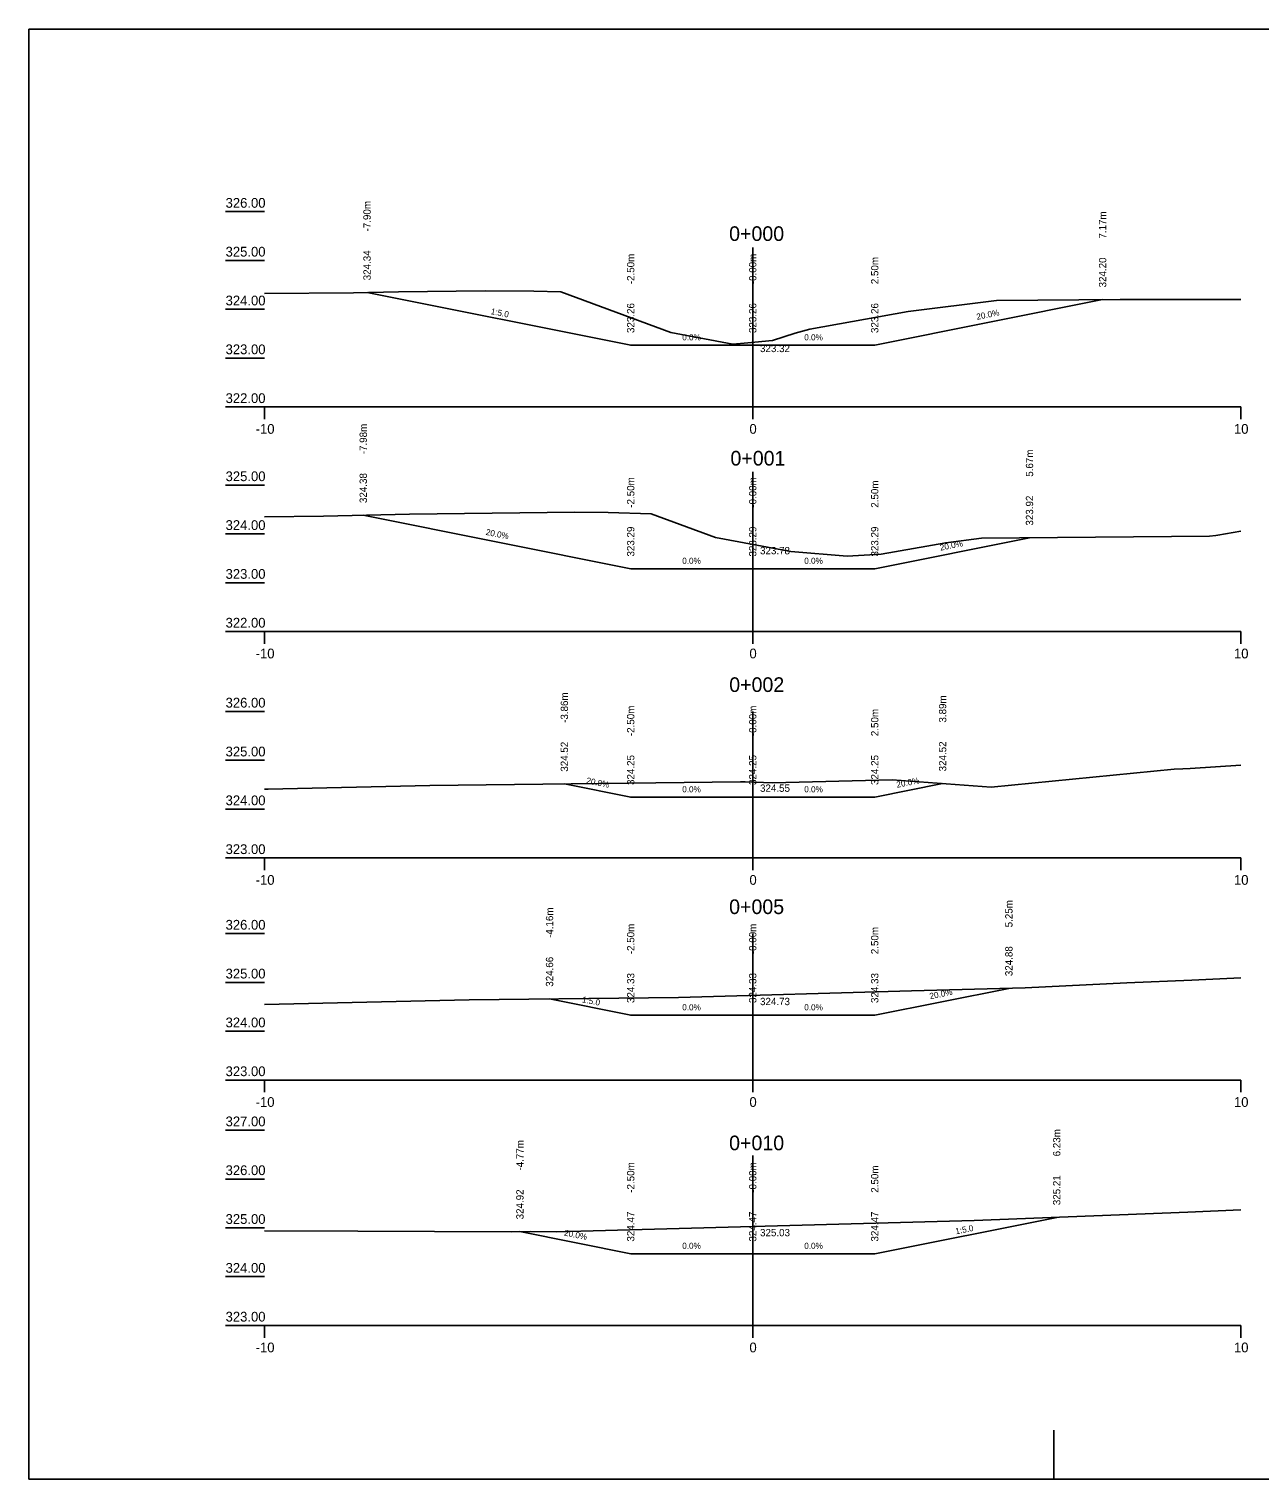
# Model space of a CAD drawing. Extents: x -559238.7 to -559196.7, y -1164066.1 to -1164036.4.
# Drawn here: x -559238.68 to -559213.47, y -1164066.1 to -1164036.4 of the extents above; entities that cross this region are included whole.
import ezdxf

# ---------------------------------------------------------------- set-up
doc = ezdxf.new("R2010")
doc.units = 0
for name, color, linetype in [('16', 7, 'Continuous'), ('21', 7, 'Continuous'), ('28', 7, 'Continuous'), ('59', 7, 'Continuous'), ('Body pricny rez', 7, 'Continuous'), ('Popis pricneho profilu', 7, 'Continuous')]:
    doc.layers.add(name, color=color, linetype=linetype)

msp = doc.modelspace()

# ---------------------------------------------------------------- linework, layer by layer
for p, q in [((-559196.676, -1164036.404), (-559238.676, -1164036.404)), ((-559238.676, -1164036.404), (-559238.676, -1164066.104)), ((-559217.676, -1164066.104), (-559217.676, -1164065.104)), ((-559238.676, -1164066.104), (-559196.676, -1164066.104))]:
    msp.add_line(p, q)
for points in [[(-559233.848, -1164041.823), (-559232.028, -1164041.807), (-559231.104, -1164041.786), (-559229.33, -1164041.765), (-559228.333, -1164041.773), (-559227.78, -1164041.79), (-559225.524, -1164042.623), (-559224.257, -1164042.858), (-559223.945, -1164042.831), (-559223.444, -1164042.783), (-559222.976, -1164042.631), (-559222.675, -1164042.551), (-559220.661, -1164042.192), (-559218.852, -1164041.967), (-559216.316, -1164041.944), (-559214.505, -1164041.941), (-559213.848, -1164041.943)], [(-559231.75, -1164041.801), (-559226.348, -1164042.881), (-559223.848, -1164042.881), (-559221.348, -1164042.881), (-559216.679, -1164041.947)], [(-559226.348, -1164042.881), (-559231.75, -1164041.801)], [(-559221.348, -1164042.881), (-559216.679, -1164041.947)], [(-559223.848, -1164042.881), (-559226.348, -1164042.881)], [(-559223.848, -1164042.881), (-559221.348, -1164042.881)], [(-559233.848, -1164046.393), (-559232.643, -1164046.382), (-559230.878, -1164046.342), (-559227.49, -1164046.302), (-559226.808, -1164046.307), (-559225.929, -1164046.334), (-559224.611, -1164046.821), (-559223.065, -1164047.108), (-559221.915, -1164047.204), (-559221.219, -1164047.162), (-559219.892, -1164046.925), (-559219.162, -1164046.834), (-559214.492, -1164046.791), (-559214.358, -1164046.776), (-559214.315, -1164046.77), (-559213.848, -1164046.691)], [(-559226.348, -1164047.459), (-559231.828, -1164046.364)], [(-559221.348, -1164047.459), (-559218.177, -1164046.825)], [(-559223.848, -1164047.459), (-559226.348, -1164047.459)], [(-559223.848, -1164047.459), (-559221.348, -1164047.459)], [(-559233.848, -1164051.974), (-559233.776, -1164051.973), (-559230.462, -1164051.899), (-559224.099, -1164051.823), (-559224, -1164051.824), (-559223.44, -1164051.841), (-559220.988, -1164051.784), (-559218.959, -1164051.933), (-559215.212, -1164051.564), (-559215.033, -1164051.556), (-559214.884, -1164051.548), (-559213.848, -1164051.485)], [(-559227.707, -1164051.866), (-559226.348, -1164052.138), (-559223.848, -1164052.138), (-559221.348, -1164052.138), (-559219.957, -1164051.86)], [(-559226.348, -1164052.138), (-559227.707, -1164051.866)], [(-559221.348, -1164052.138), (-559219.957, -1164051.86)], [(-559223.848, -1164052.138), (-559226.348, -1164052.138)], [(-559223.848, -1164052.138), (-559221.348, -1164052.138)], [(-559233.848, -1164056.385), (-559229.656, -1164056.291), (-559225.369, -1164056.24), (-559220.597, -1164056.108), (-559218.263, -1164056.045), (-559216.183, -1164055.942), (-559214.849, -1164055.886), (-559213.848, -1164055.84)], [(-559228.011, -1164056.271), (-559226.348, -1164056.604), (-559223.848, -1164056.604), (-559221.348, -1164056.604), (-559218.6, -1164056.054)], [(-559221.348, -1164056.604), (-559218.6, -1164056.054)], [(-559226.348, -1164056.604), (-559228.011, -1164056.271)], [(-559223.848, -1164056.604), (-559226.348, -1164056.604)], [(-559223.848, -1164056.604), (-559221.348, -1164056.604)], [(-559233.848, -1164061.023), (-559231.941, -1164061.03), (-559228.796, -1164061.04), (-559228.391, -1164061.032), (-559227.875, -1164061.038), (-559219.312, -1164060.811), (-559214.933, -1164060.639), (-559213.848, -1164060.589)], [(-559221.348, -1164061.49), (-559217.62, -1164060.745)], [(-559226.348, -1164061.49), (-559228.618, -1164061.036)], [(-559223.848, -1164061.49), (-559226.348, -1164061.49)], [(-559223.848, -1164061.49), (-559221.348, -1164061.49)]]:
    msp.add_lwpolyline(points)
at = {"layer": '16'}
for p, q in [((-559233.848, -1164044.145), (-559213.848, -1164044.145)), ((-559233.848, -1164048.745), (-559213.848, -1164048.745)), ((-559233.848, -1164053.383), (-559213.848, -1164053.383)), ((-559233.848, -1164057.932), (-559213.848, -1164057.932)), ((-559233.848, -1164062.959), (-559213.848, -1164062.959))]:
    msp.add_line(p, q, dxfattribs=at)
at = {"layer": '21'}
for p, q in [((-559234.648, -1164040.145), (-559233.848, -1164040.145)), ((-559234.648, -1164041.145), (-559233.848, -1164041.145)), ((-559234.648, -1164042.145), (-559233.848, -1164042.145)), ((-559234.648, -1164043.145), (-559233.848, -1164043.145)), ((-559234.648, -1164044.145), (-559233.848, -1164044.145)), ((-559234.648, -1164045.745), (-559233.848, -1164045.745)), ((-559234.648, -1164046.745), (-559233.848, -1164046.745)), ((-559234.648, -1164047.745), (-559233.848, -1164047.745)), ((-559234.648, -1164048.745), (-559233.848, -1164048.745)), ((-559234.648, -1164050.383), (-559233.848, -1164050.383)), ((-559234.648, -1164051.383), (-559233.848, -1164051.383)), ((-559234.648, -1164052.383), (-559233.848, -1164052.383)), ((-559234.648, -1164053.383), (-559233.848, -1164053.383)), ((-559234.648, -1164054.932), (-559233.848, -1164054.932)), ((-559234.648, -1164055.932), (-559233.848, -1164055.932)), ((-559234.648, -1164056.932), (-559233.848, -1164056.932)), ((-559234.648, -1164057.932), (-559233.848, -1164057.932)), ((-559234.648, -1164058.959), (-559233.848, -1164058.959)), ((-559234.648, -1164059.959), (-559233.848, -1164059.959)), ((-559234.648, -1164060.959), (-559233.848, -1164060.959)), ((-559234.648, -1164061.959), (-559233.848, -1164061.959)), ((-559234.648, -1164062.959), (-559233.848, -1164062.959))]:
    msp.add_line(p, q, dxfattribs=at)
at = {"layer": '28'}
for p, q in [((-559223.848, -1164040.878), (-559223.848, -1164044.145)), ((-559223.848, -1164045.471), (-559223.848, -1164048.745)), ((-559223.848, -1164050.383), (-559223.848, -1164053.383)), ((-559223.848, -1164054.932), (-559223.848, -1164057.932)), ((-559223.848, -1164059.475), (-559223.848, -1164062.959))]:
    msp.add_line(p, q, dxfattribs=at)
at = {"layer": '59'}
for p, q in [((-559233.848, -1164044.395), (-559233.848, -1164044.145)), ((-559223.848, -1164044.395), (-559223.848, -1164044.145)), ((-559213.848, -1164044.395), (-559213.848, -1164044.145)), ((-559233.848, -1164048.995), (-559233.848, -1164048.745)), ((-559223.848, -1164048.995), (-559223.848, -1164048.745)), ((-559213.848, -1164048.995), (-559213.848, -1164048.745)), ((-559233.848, -1164053.633), (-559233.848, -1164053.383)), ((-559223.848, -1164053.633), (-559223.848, -1164053.383)), ((-559213.848, -1164053.633), (-559213.848, -1164053.383)), ((-559233.848, -1164058.182), (-559233.848, -1164057.932)), ((-559223.848, -1164058.182), (-559223.848, -1164057.932)), ((-559213.848, -1164058.182), (-559213.848, -1164057.932)), ((-559233.848, -1164063.209), (-559233.848, -1164062.959)), ((-559223.848, -1164063.209), (-559223.848, -1164062.959)), ((-559213.848, -1164063.209), (-559213.848, -1164062.959))]:
    msp.add_line(p, q, dxfattribs=at)

# ---------------------------------------------------------------- texts
for s, p in [('0+000', (-559224.331, -1164040.745)), ('0+001', (-559224.304, -1164045.345)), ('0+002', (-559224.329, -1164049.983)), ('0+005', (-559224.331, -1164054.532)), ('0+010', (-559224.331, -1164059.37))]:
    msp.add_text(s, height=0.3).set_placement(p)
for rotation, p in [(348.6901, (-559229.223, -1164042.242)), (348.6901, (-559227.353, -1164056.339)), (11.3099, (-559219.682, -1164061.093))]:
    msp.add_text('1:5.0', height=0.125, rotation=rotation).set_placement(p)
at = {"layer": '16'}
for rotation, p in [(11.3099, (-559219.251, -1164042.362)), (348.6901, (-559229.325, -1164046.764)), (11.3099, (-559220, -1164047.09)), (348.6901, (-559227.265, -1164051.854)), (11.3099, (-559220.89, -1164051.946)), (11.3099, (-559220.212, -1164056.277)), (348.6901, (-559227.72, -1164061.116))]:
    msp.add_text('20.0%', height=0.125, rotation=rotation, dxfattribs=at).set_placement(p)
for p in [(-559225.292, -1164042.781), (-559222.792, -1164042.781), (-559225.292, -1164047.359), (-559222.792, -1164047.359), (-559225.292, -1164052.038), (-559222.792, -1164052.038), (-559225.292, -1164056.504), (-559222.792, -1164056.504), (-559225.292, -1164061.39), (-559222.792, -1164061.39)]:
    msp.add_text('0.0%', height=0.125, dxfattribs=at).set_placement(p)
at = {"layer": '21'}
for s, p in [('326.00', (-559234.648, -1164040.065)), ('325.00', (-559234.648, -1164041.065)), ('324.00', (-559234.648, -1164042.065)), ('323.00', (-559234.648, -1164043.065)), ('322.00', (-559234.648, -1164044.065)), ('-10', (-559234.032, -1164044.695)), ('0', (-559223.915, -1164044.695)), ('10', (-559213.988, -1164044.695)), ('325.00', (-559234.648, -1164045.665)), ('324.00', (-559234.648, -1164046.665)), ('323.00', (-559234.648, -1164047.665)), ('322.00', (-559234.648, -1164048.665)), ('-10', (-559234.032, -1164049.295)), ('0', (-559223.915, -1164049.295)), ('10', (-559213.988, -1164049.295)), ('326.00', (-559234.648, -1164050.303)), ('325.00', (-559234.648, -1164051.303)), ('324.00', (-559234.648, -1164052.303)), ('323.00', (-559234.648, -1164053.303)), ('-10', (-559234.032, -1164053.933)), ('0', (-559223.915, -1164053.933)), ('10', (-559213.988, -1164053.933)), ('326.00', (-559234.648, -1164054.852)), ('325.00', (-559234.648, -1164055.852)), ('324.00', (-559234.648, -1164056.852)), ('323.00', (-559234.648, -1164057.852)), ('-10', (-559234.032, -1164058.482)), ('0', (-559223.915, -1164058.482)), ('10', (-559213.988, -1164058.482)), ('327.00', (-559234.648, -1164058.879)), ('326.00', (-559234.648, -1164059.879)), ('325.00', (-559234.648, -1164060.879)), ('324.00', (-559234.648, -1164061.879)), ('323.00', (-559234.648, -1164062.879)), ('-10', (-559234.032, -1164063.509)), ('0', (-559223.915, -1164063.509)), ('10', (-559213.988, -1164063.509))]:
    msp.add_text(s, height=0.2, dxfattribs=at).set_placement(p)
at = {"layer": '59'}
for s, p in [('323.32', (-559223.698, -1164043.022)), ('323.78', (-559223.698, -1164047.163)), ('324.55', (-559223.698, -1164052.028)), ('324.73', (-559223.698, -1164056.398)), ('325.03', (-559223.698, -1164061.132))]:
    msp.add_text(s, height=0.15, dxfattribs=at).set_placement(p)
at = {"layer": 'Body pricny rez'}
for p in [(-559231.751, -1164041.801), (-559216.68, -1164041.948), (-559226.349, -1164042.882), (-559223.849, -1164042.882), (-559221.349, -1164042.882), (-559231.828, -1164046.364), (-559218.177, -1164046.826), (-559226.349, -1164047.46), (-559223.849, -1164047.46), (-559221.349, -1164047.46), (-559227.708, -1164051.867), (-559219.958, -1164051.86), (-559226.349, -1164052.138), (-559223.849, -1164052.138), (-559221.349, -1164052.138), (-559218.601, -1164056.055), (-559228.011, -1164056.272), (-559226.349, -1164056.604), (-559223.849, -1164056.604), (-559221.349, -1164056.604), (-559217.62, -1164060.745), (-559228.618, -1164061.037), (-559226.349, -1164061.491), (-559223.849, -1164061.491), (-559221.349, -1164061.491)]:
    msp.add_text('+', height=0.001, dxfattribs=at).set_placement(p)
at = {"layer": 'Popis pricneho profilu'}
for s, p in [('-7.90m', (-559231.675, -1164040.551)), ('7.17m', (-559216.604, -1164040.697)), ('324.34', (-559231.675, -1164041.551)), ('-2.50m', (-559226.273, -1164041.631)), ('-0.00m', (-559223.773, -1164041.631)), ('2.50m', (-559221.273, -1164041.631)), ('324.20', (-559216.604, -1164041.697)), ('323.26', (-559226.273, -1164042.631)), ('323.26', (-559223.773, -1164042.631)), ('323.26', (-559221.273, -1164042.631)), ('-7.98m', (-559231.753, -1164045.114)), ('5.67m', (-559218.102, -1164045.575)), ('324.38', (-559231.753, -1164046.114)), ('-2.50m', (-559226.273, -1164046.209)), ('-0.00m', (-559223.773, -1164046.209)), ('2.50m', (-559221.273, -1164046.209)), ('323.92', (-559218.102, -1164046.575)), ('323.29', (-559226.273, -1164047.209)), ('323.29', (-559223.773, -1164047.209)), ('323.29', (-559221.273, -1164047.209)), ('-3.86m', (-559227.632, -1164050.616)), ('3.89m', (-559219.882, -1164050.61)), ('-2.50m', (-559226.273, -1164050.888)), ('-0.00m', (-559223.773, -1164050.888)), ('2.50m', (-559221.273, -1164050.888)), ('324.52', (-559227.632, -1164051.616)), ('324.52', (-559219.882, -1164051.61)), ('324.25', (-559226.273, -1164051.888)), ('324.25', (-559223.773, -1164051.888)), ('324.25', (-559221.273, -1164051.888)), ('5.25m', (-559218.525, -1164054.804)), ('-4.16m', (-559227.936, -1164055.021)), ('-2.50m', (-559226.273, -1164055.354)), ('-0.00m', (-559223.773, -1164055.354)), ('2.50m', (-559221.273, -1164055.354)), ('324.88', (-559218.525, -1164055.804)), ('324.66', (-559227.936, -1164056.021)), ('324.33', (-559226.273, -1164056.354)), ('324.33', (-559223.773, -1164056.354)), ('324.33', (-559221.273, -1164056.354)), ('6.23m', (-559217.545, -1164059.495)), ('-4.77m', (-559228.543, -1164059.786)), ('-2.50m', (-559226.273, -1164060.24)), ('-0.00m', (-559223.773, -1164060.24)), ('2.50m', (-559221.273, -1164060.24)), ('325.21', (-559217.545, -1164060.495)), ('324.92', (-559228.543, -1164060.786)), ('324.47', (-559226.273, -1164061.24)), ('324.47', (-559223.773, -1164061.24)), ('324.47', (-559221.273, -1164061.24))]:
    msp.add_text(s, height=0.15, rotation=90, dxfattribs=at).set_placement(p)

doc.saveas('drawing.dxf')
